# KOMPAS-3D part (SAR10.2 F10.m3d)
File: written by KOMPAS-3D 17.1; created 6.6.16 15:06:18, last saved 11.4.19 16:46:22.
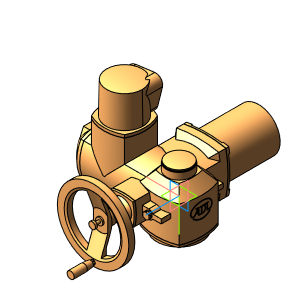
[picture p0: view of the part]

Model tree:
1. Операция без истории:4  (labels: Сталь 20  ГОСТ 1050-88)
